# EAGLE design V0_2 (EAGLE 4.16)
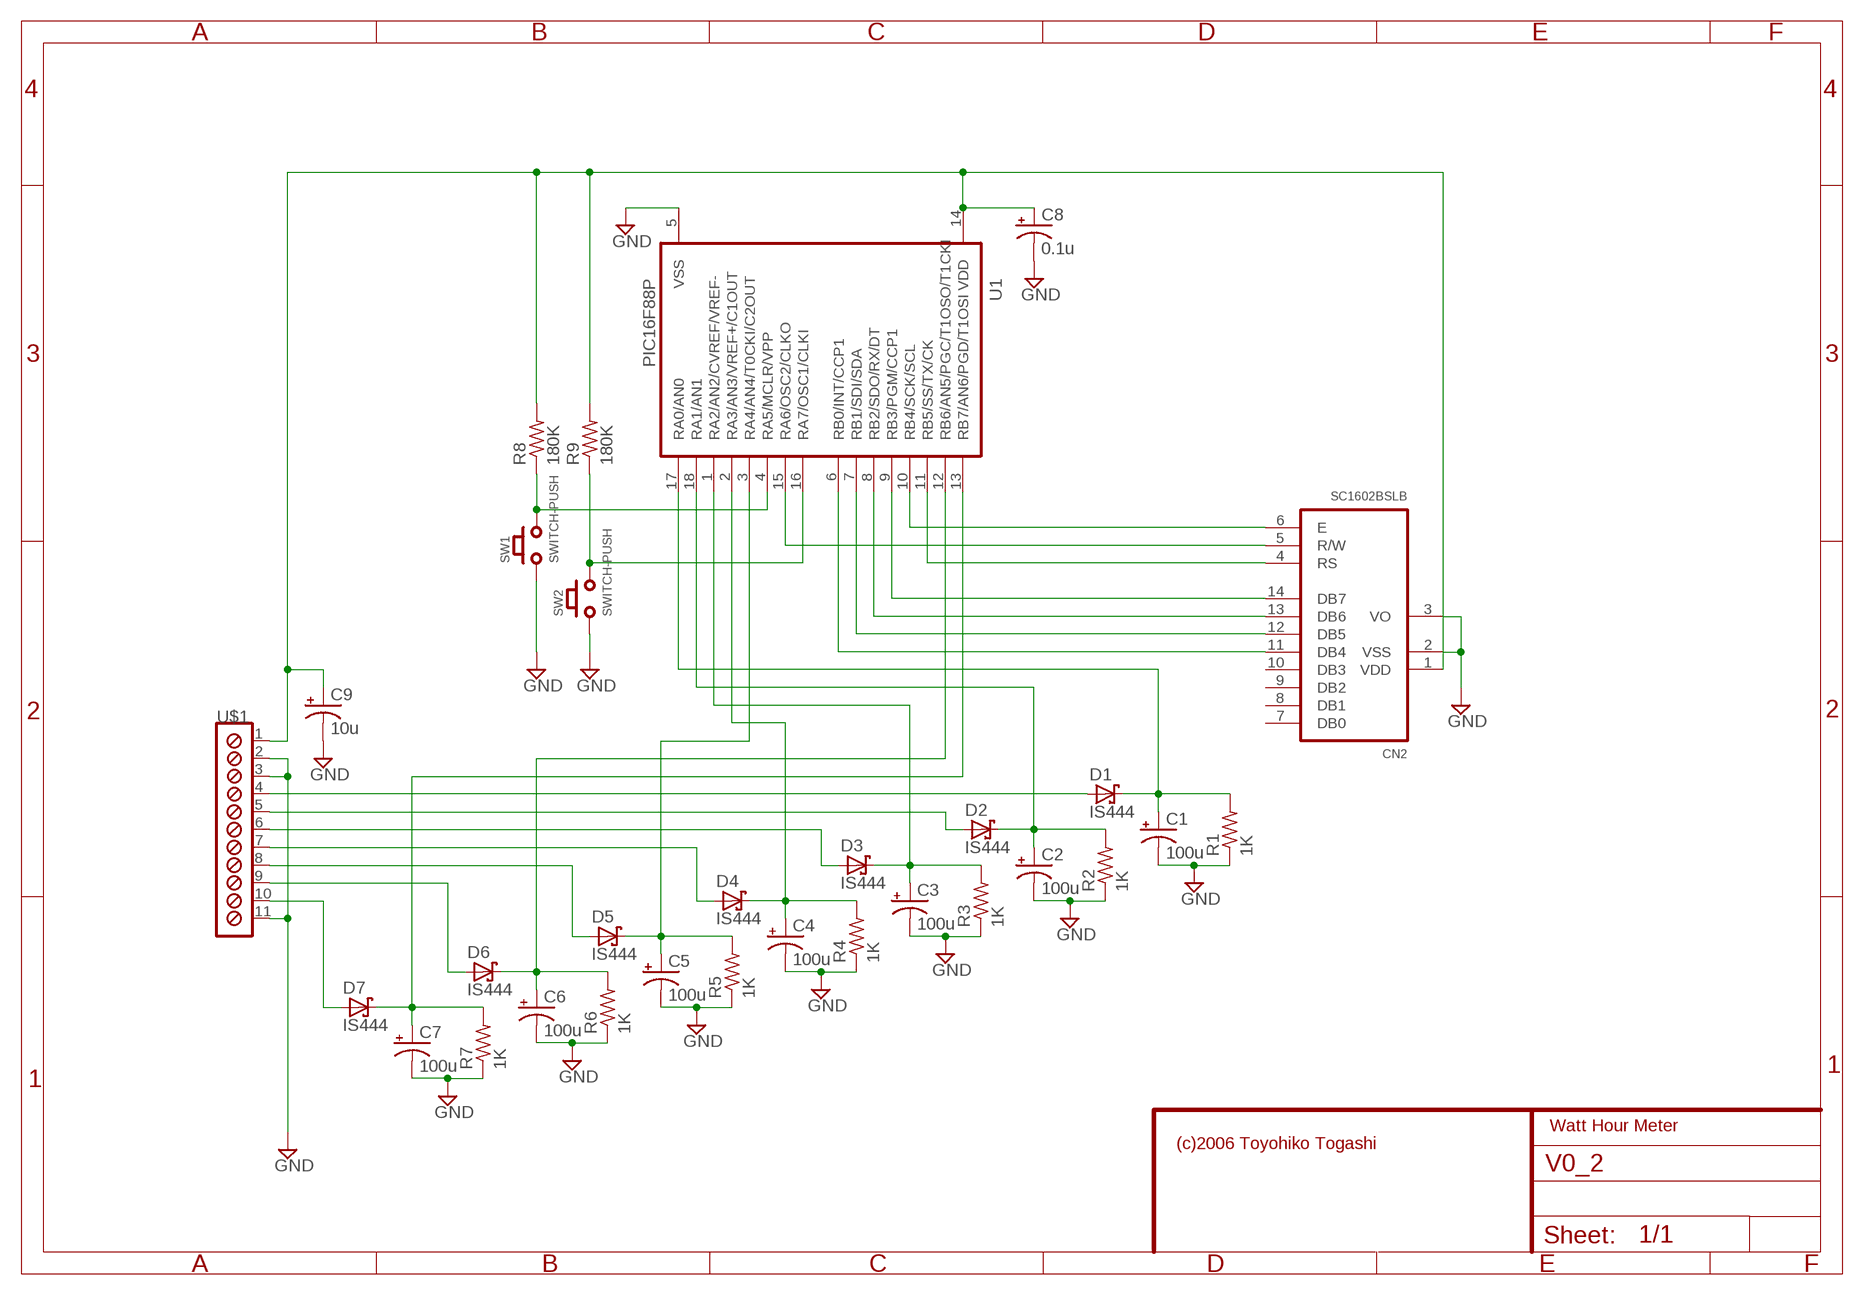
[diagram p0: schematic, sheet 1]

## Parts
C1  100u  CPOL-USE2.5-6  [E2,5-6]
C2  100u  CPOL-USE2.5-6  [E2,5-6]
C3  100u  CPOL-USE2.5-6  [E2,5-6]
C4  100u  CPOL-USE2.5-6  [E2,5-6]
C5  100u  CPOL-USE2.5-6  [E2,5-6]
C6  100u  CPOL-USE2.5-6  [E2,5-6]
C7  100u  CPOL-USE2.5-6  [E2,5-6]
C8  0.1u  CPOL-USE2.5-6  [E2,5-6]
C9  10u  CPOL-USE2.5-6  [E2,5-6]
CN2  SC1602BSLB  [MA07-2]
D1  IS444  SCHOTTKY-DIODEDO35-7  [DO35-7]
D2  IS444  SCHOTTKY-DIODEDO35-7  [DO35-7]
D3  IS444  SCHOTTKY-DIODEDO35-7  [DO35-7]
D4  IS444  SCHOTTKY-DIODEDO35-7  [DO35-7]
D5  IS444  SCHOTTKY-DIODEDO35-7  [DO35-7]
D6  IS444  SCHOTTKY-DIODEDO35-7  [DO35-7]
D7  IS444  SCHOTTKY-DIODEDO35-7  [DO35-7]
R1  1K  R-US_0204/7  [0204/7]
R2  1K  R-US_0204/7  [0204/7]
R3  1K  R-US_0204/7  [0204/7]
R4  1K  R-US_0204/7  [0204/7]
R5  1K  R-US_0204/7  [0204/7]
R6  1K  R-US_0204/7  [0204/7]
R7  1K  R-US_0204/7  [0204/7]
R8  180K  R-US_0204/7  [0204/7]
R9  180K  R-US_0204/7  [0204/7]
SW1  SWITCH-PUSH  [SWITCH-PUSH]
SW2  SWITCH-PUSH  [SWITCH-PUSH]
U1  PIC16F88P  [DIL18]
U$1  CONN-SCREW-11P  [CONN-SCREW-11P]

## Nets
CN1: C8.+ C9.+ CN2.1(VDD) R8.2 R9.2 U1.14(VDD) U$1.1
GND: C1.- C2.- C3.- C4.- C5.- C6.- C7.- C8.- C9.- CN2.2(VSS) CN2.3(VO) R1.1 R2.1 R3.1 R4.1 R5.1 R6.1 R7.1 SW1.P$1(A1) SW2.P$1(A1) U1.5(VSS) U$1.2 U$1.3 U$1.11
N$1: C1.+ D1.C R1.2 U1.17(RA0/AN0)
N$2: C3.+ D3.C R3.2 U1.1(RA2/AN2/CVREF/VREF-)
N$3: C2.+ D2.C R2.2 U1.18(RA1/AN1)
N$4: C4.+ D4.C R4.2 U1.2(RA3/AN3/VREF+/C1OUT)
N$5: C5.+ D5.C R5.2 U1.3(RA4/AN4/T0CKI/C2OUT)
N$6: C6.+ D6.C R6.2 U1.12(RB6/AN5/PGC/T1OSO/T1CKI)
N$7: C7.+ D7.C R7.2 U1.13(RB7/AN6/PGD/T1OSI)
N$8: D1.A U$1.4
N$9: D2.A U$1.5
N$10: D3.A U$1.6
N$11: D4.A U$1.7
N$12: D5.A U$1.8
N$13: D6.A U$1.9
N$14: D7.A U$1.10
N$15: CN2.11(DB4) U1.6(RB0/INT/CCP1)
N$16: CN2.12(DB5) U1.7(RB1/SDI/SDA)
N$17: CN2.13(DB6) U1.8(RB2/SDO/RX/DT)
N$18: CN2.14(DB7) U1.9(RB3/PGM/CCP1)
N$19: CN2.4(RS) U1.11(RB5/SS/TX/CK)
N$20: CN2.5(R/W) U1.15(RA6/OSC2/CLKO)
N$21: CN2.6(E) U1.10(RB4/SCK/SCL)
N$23: R8.1 SW1.P$2(A2) U1.4(RA5/MCLR/VPP)
N$24: R9.1 SW2.P$2(A2) U1.16(RA7/OSC1/CLKI)
Unconnected: CN2.7(DB0) CN2.8(DB1) CN2.9(DB2) CN2.10(DB3)

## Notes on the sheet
- Watt Hour Meter
- (c)2006 Toyohiko Togashi

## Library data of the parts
C1-C9 = rcl:CPOL-US: POLARIZED CAPACITOR, American symbol
CN2 = TOG:SC1602BSLB
D1-D7 = diode:SCHOTTKY-DIODE: Schottky Diode
R1-R9 = rcl:R-US_: RESISTOR, American symbol
SW1 SW2 = TOG:SWITCH-PUSH
U1 = microchip:PIC16F88
U$1 = TOG:CONN-SCREW-11P

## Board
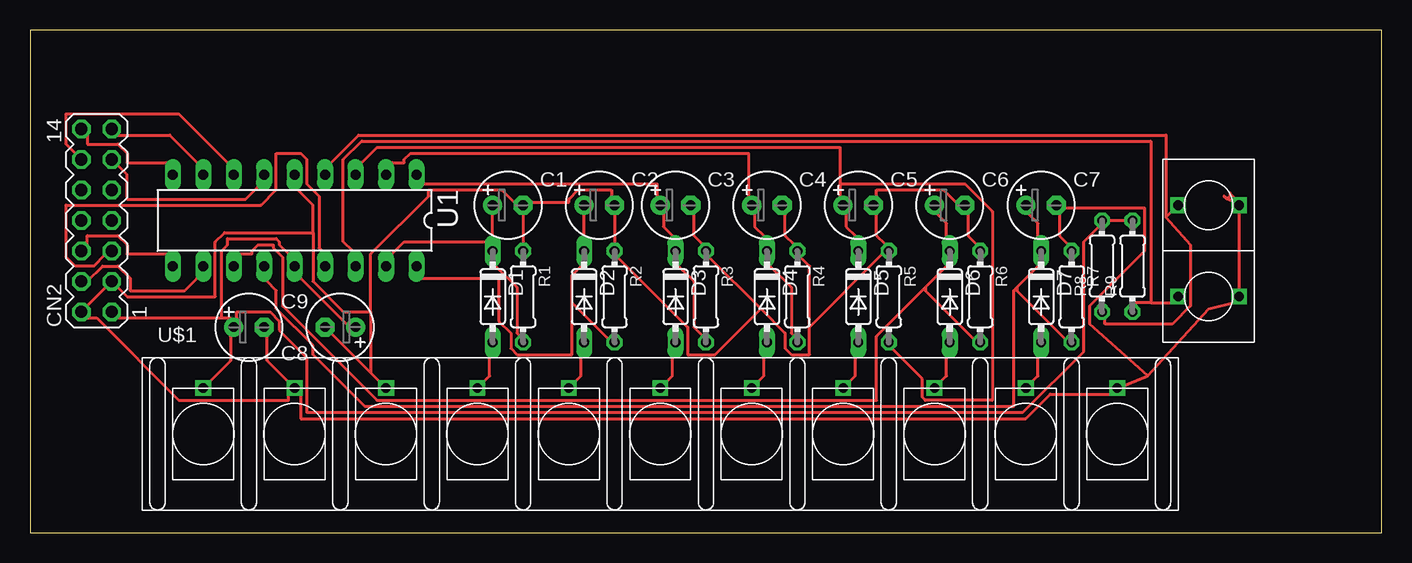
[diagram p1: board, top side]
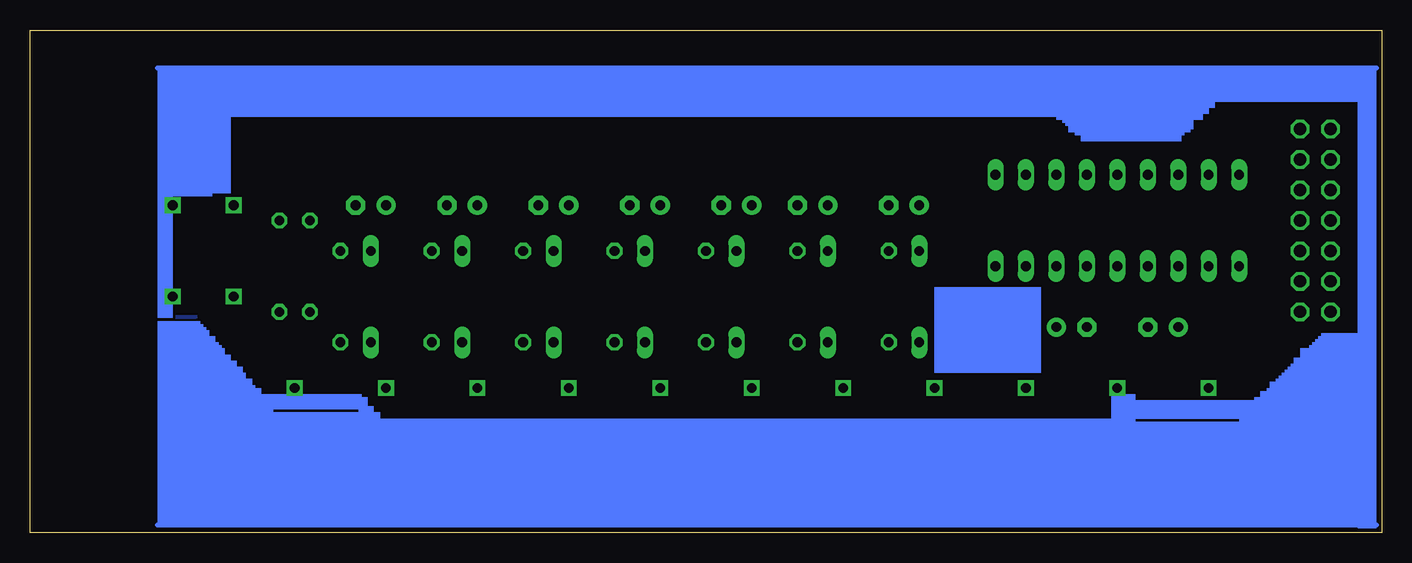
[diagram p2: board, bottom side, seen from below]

Size 112.7 x 41.9 mm. Coordinates in mm from the lower left corner, seen from the top.
Outline: 0,0 112.7,0 112.7,41.9 0,41.9 0,0
Copper layers (1*16): Top 0.035mm / dielectric 1.5mm / Bottom 0.035mm
Design rules "default": minimum track width 10mil, minimum drill 24mil, track to track 8mil, track to pad 8mil, pad to pad 8mil, via to via 8mil, smd to smd 8mil, copper to edge 40mil, drill to drill 8mil, minimum pad ring 10mil, minimum via ring 8mil, stop-mask expansion 4mil, vias tented up to drill 0mil, thermal gap 10mil

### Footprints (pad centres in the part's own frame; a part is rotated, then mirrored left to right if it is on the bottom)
E2,5-6 = drill 0.813 pad 1.6 round: + -1.27,0 | drill 0.813 pad 1.6 octagon: - 1.27,0
MA07-2 = drill 1.016 octagon: 1 -7.62,-1.27; 2 -7.62,1.27; 3 -5.08,-1.27; 4 -5.08,1.27; 5 -2.54,-1.27; 6 -2.54,1.27; 7 0,-1.27; 8 0,1.27; 9 2.54,-1.27; 10 2.54,1.27; 11 5.08,-1.27; 12 5.08,1.27; 13 7.62,-1.27; 14 7.62,1.27
DO35-7 = drill 0.813 long: A 3.81,0; C -3.81,0
0204/7 = drill 0.813 octagon: 1 -3.81,0; 2 3.81,0
SWITCH-PUSH = drill 0.8 square: P$1 0,2.54; P$2 0,-2.54
DIL18 = drill 0.813 long: 1 -10.16,-3.81; 2 -7.62,-3.81; 3 -5.08,-3.81; 4 -2.54,-3.81; 5 0,-3.81; 6 2.54,-3.81; 7 5.08,-3.81; 8 7.62,-3.81; 9 10.16,-3.81; 10 10.16,3.81; 11 7.62,3.81; 12 5.08,3.81; 13 2.54,3.81; 14 0,3.81; 15 -2.54,3.81; 16 -5.08,3.81; 17 -7.62,3.81; 18 -10.16,3.81
CONN-SCREW-11P = drill 0.8 square: 1 -38.1,3.81; 2 -30.48,3.81; 3 -22.86,3.81; 4 -15.24,3.81; 5 -7.62,3.81; 6 0,3.81; 7 7.62,3.81; 8 15.24,3.81; 9 22.86,3.81; 10 30.48,3.81; 11 38.1,3.81

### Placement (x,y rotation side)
C1  39.84,27.3 0 top
C2  47.46,27.3 0 top
C3  53.81,27.3 0 top
C4  61.43,27.3 0 top
C5  69.05,27.3 0 top
C6  76.67,27.3 0 top
C7  84.29,27.3 0 top
C8  25.87,17.14 180 top
C9  18.25,17.14 0 top
CN2  5.55,26.03 90 top
D1  38.57,19.68 270 top
D2  46.19,19.68 270 top
D3  53.81,19.68 270 top
D4  61.43,19.68 270 top
D5  69.05,19.68 270 top
D6  76.67,19.68 270 top
D7  84.29,19.68 270 top
R1  41.11,19.68 270 top
R2  48.73,19.68 270 top
R3  56.35,19.68 270 top
R4  63.97,19.68 270 top
R5  71.59,19.68 270 top
R6  79.21,19.68 270 top
R7  86.83,19.68 270 top
R8  89.37,22.22 90 top
R9  91.91,22.22 90 top
SW1  98.26,27.3 270 top
SW2  98.26,19.68 270 top
U1  22.06,26.03 180 top
U$1  52.54,8.25 0 top

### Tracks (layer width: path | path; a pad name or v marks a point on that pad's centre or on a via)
CN1
  Top 0.254: C8.+ 26.38,17.39 22.57,21.2 U1.14 21.55,23.24 20.79,24 20.79,24.25 20.54,24.51 16.47,24.51 16.47,24 15.96,23.49 15.96,17.9 | R9.2 R8.2 89.12,25.52 87.85,24.25 87.85,15.11 82.77,10.03 23.08,10.03 23.08,14.6 20.79,16.89 20.79,17.65 20.03,18.41 17.23,18.41 17.23,17.9 C9.+ | U$1.1 16.73,14.35 16.73,16.38 C9.+ | 15.96,17.9 16.73,17.9 C9.+ | 15.96,17.9 7.33,17.9 CN2.1
GND
  Top 0.254: R6.1 78.96,24 78.19,24.76 78.19,26.54 C6.- 77.18,27.55 76.16,28.57 70.57,28.57 70.57,28.06 C5.- 70.57,26.54 70.57,24.76 71.34,24 R5.1 71.08,23.24 64.99,17.14 | C3.- 55.33,26.54 55.33,24.76 56.1,24 R3.1 56.6,22.98 60.92,18.66 | C4.- 62.95,26.54 62.95,24.76 63.72,24 R4.1 64.22,22.98 64.99,22.22 64.99,17.14 | 60.92,18.66 62.95,16.63 62.95,15.36 63.46,14.85 64.99,14.85 64.99,17.14 | R7.1 86.58,24 85.81,24.76 85.81,26.54 C7.- 86.32,27.05 92.93,27.05 92.93,23.49 88.35,18.92 88.35,17.39 93.18,13.08 | 93.18,13.08 98.26,18.66 100.29,19.17 SW2.P$1 100.8,27.55 100.04,28.32 100.04,28.06 99.78,27.81 99.53,28.06 SW1.P$1 | 93.18,13.08 U$1.11 90.13,11.55 85.05,11.55 83.02,9.52 22.57,9.52 22.57,11.55 U$1.2 | U$1.2 19.77,14.35 19.77,16.38 C9.- | U$1.2 21.55,11.55 21.55,11.04 12.41,11.04 5.55,17.9 4.79,17.9 CN2.2 CN2.3 8.09,19.68 15.46,19.68 15.46,24.25 16.22,25.01 23.58,25.01 | C1.- R1.1 | C1.- 41.87,27.55 44.92,27.55 44.92,27.81 45.68,28.57 48.48,28.57 48.48,28.06 C2.- R2.1 48.98,22.98 54.83,17.14 54.83,14.85 57.11,14.85 60.92,18.66 | 28.41,13.33 U$1.3 | 28.41,13.33 C8.- | 23.58,25.01 23.58,20.95 26.12,18.41 28.41,18.41 | 23.58,25.01 23.58,27.3 22.31,28.57 U1.5 | 28.41,18.41 28.41,13.33 | 28.41,18.41 28.41,23.24 33.24,28.06 33.24,28.57 39.33,28.57 40.35,27.55 C1.-
N$1
  Top 0.254: U1.17 30.19,23.24 31.2,24.25 38.06,24.25 D1.C | R1.2 40.86,16.38 40.6,16.63 40.6,20.44 38.82,22.22 D1.C | D1.C C1.+
N$2
  Top 0.254: U1.1 32.73,29.08 52.29,29.08 52.29,28.06 C3.+ 52.79,26.54 52.79,25.52 53.56,24.76 D3.C 54.06,22.22 55.33,20.95 55.33,17.14 56.1,16.38 R3.2
N$3
  Top 0.254: 45.17,19.17 45.17,21.46 45.94,22.22 D2.C C2.+ | 45.17,19.17 45.17,14.85 40.6,14.85 40.09,15.36 40.09,16.63 39.08,17.65 39.08,21.2 32.73,21.2 U1.18 | 45.17,19.17 48.22,16.12 R2.2
N$4
  Top 0.254: U1.2 30.19,30.86 31.2,30.86 31.2,31.11 31.71,31.62 59.91,31.62 59.91,28.06 C4.+ 60.41,26.54 60.41,25.52 61.18,24.76 D4.C 61.68,22.22 63.46,20.44 63.46,16.63 63.72,16.38 R4.2
N$5
  Top 0.254: 67.53,29.08 67.53,28.06 C5.+ 68.03,26.54 68.03,25.52 68.8,24.76 D5.C | 67.53,29.08 67.53,32.13 28.92,32.13 27.65,30.86 U1.3 | 67.53,29.08 77.94,29.08 80.23,26.79 80.23,11.04 74.64,11.04 74.38,11.3 74.38,12.82 71.84,15.36 R5.2
N$6
  Top 0.254: 74.64,20.44 76.42,22.22 D6.C 76.42,24.76 76.42,25.78 75.65,26.54 C6.+ | 74.64,20.44 70.57,16.38 70.57,11.04 28.92,11.04 21.04,18.92 21.04,22.98 20.28,23.74 20.28,24 19.01,24 18.5,23.49 18.5,23.24 17.49,23.24 U1.12 | 74.64,20.44 74.64,20.19 78.7,16.12 R6.2
N$7
  Top 0.254: 82.26,20.44 84.04,22.22 D7.C 84.04,24.76 84.04,25.78 83.27,26.54 C7.+ | 82.26,20.44 82,20.19 82,10.54 27.9,10.54 23.58,14.85 23.58,15.62 20.54,18.66 20.54,20.19 19.77,20.95 U1.13 | 82.26,20.44 82.26,20.19 86.32,16.12 R7.2
N$8
  Top 0.254: U$1.4 38.32,13.08 38.32,14.6 D1.A
N$9
  Top 0.254: U$1.5 45.94,13.08 45.94,14.6 D2.A
N$10
  Top 0.254: U$1.6 53.56,13.08 53.56,14.6 D3.A
N$11
  Top 0.254: U$1.7 61.18,13.08 61.18,14.6 D4.A
N$12
  Top 0.254: U$1.8 68.8,13.08 68.8,14.6 D5.A
N$13
  Top 0.254: U$1.9 76.42,13.08 76.42,14.6 D6.A
N$14
  Top 0.254: U$1.10 84.04,13.08 84.04,14.6 D7.A
N$15
  Top 0.254: U1.6 19.01,28.82 18,27.81 8.09,27.81 8.09,29.84 CN2.11
N$16
  Top 0.254: U1.7 16.47,30.86 12.41,34.92 3.01,34.92 3.01,32.38 CN2.12
N$17
  Top 0.254: U1.8 13.93,30.86 11.65,33.14 7.33,33.14 CN2.13
N$18
  Top 0.254: U1.9 11.39,30.86 8.09,30.86 8.09,31.62 7.33,32.38 4.79,32.38 4.79,33.14 CN2.14
N$19
  Top 0.254: U1.11 13.93,21.2 12.92,20.19 8.34,20.19 8.34,21.2 7.33,22.22 6.06,22.22 4.79,20.95 CN2.4
N$20
  Top 0.254: U1.15 24.35,23.49 24.09,23.74 24.09,28.06 23.08,29.08 23.08,31.11 22.57,31.62 20.54,31.62 20.54,28.57 19.27,27.3 3.01,27.3 3.01,22.98 3.77,22.22 5.3,22.22 6.31,23.24 CN2.5
N$21
  Top 0.254: U1.10 11.39,23.24 8.09,23.24 8.09,24 7.33,24.76 4.79,24.76 4.79,24 CN2.6
N$22
  Bottom 0.406: 0.47,38.73 102.07,38.73
N$23
  Top 0.254: 94.7,26.28 96.74,24 96.74,18.92 95.21,17.39 89.62,17.39 89.62,17.9 R8.1 | 94.7,26.28 SW1.P$2 | 94.7,26.28 94.7,33.14 27.39,33.14 25.11,30.86 U1.4
N$24
  Top 0.254: 93.43,19.17 92.16,19.17 92.16,18.92 R9.1 | 93.43,19.17 95.21,19.17 SW2.P$2 | 93.43,19.17 93.43,32.63 27.65,32.63 26.12,31.11 26.12,24.25 26.89,23.49 U1.16
N$25
  pour Bottom: 0.47,16.63 5.04,16.63 12.15,9.52 21.55,9.52 21.55,8.5 83.78,8.5 85.56,10.28 92.16,10.28 98.77,17.9 102.07,17.9 102.07,0.63 0.47,0.63
N$26
  pour Bottom (no thermals): 0.47,36.19 13.42,36.19 16.98,32.63 24.85,32.63 27.14,34.67 95.97,34.67 95.97,29.33 102.07,29.33 102.07,38.73 0.47,38.73
N$27
  Bottom 0.406: 0.47,0.63 102.07,0.63
(copper drawn outside any net)
  shapes: Bottom area x74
